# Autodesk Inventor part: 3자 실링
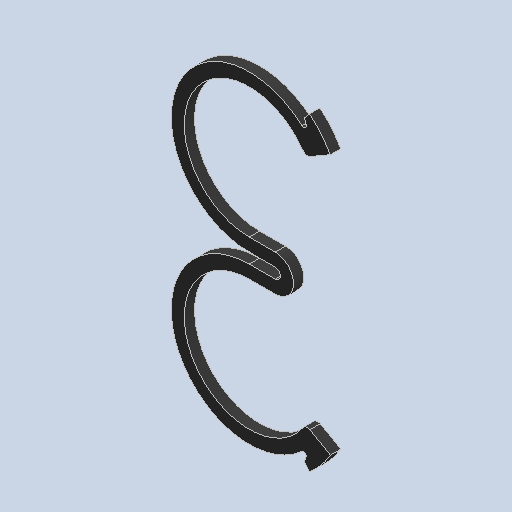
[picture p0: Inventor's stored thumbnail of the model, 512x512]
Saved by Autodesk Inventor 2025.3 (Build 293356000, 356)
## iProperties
Created: 2025-10
Part Number: 3자 실링
Material: 고무
Document SubType Name: Modeling
Designer: PC-04
Density: 0.93 g/cm^3
Appearance: 기본값
Author: jhkim
Sending System: Autodesk Inventor 2026
Preprocessor: ST-DEVELOPER v20.1
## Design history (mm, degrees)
feature "솔리드1"
node "솔리드2"
